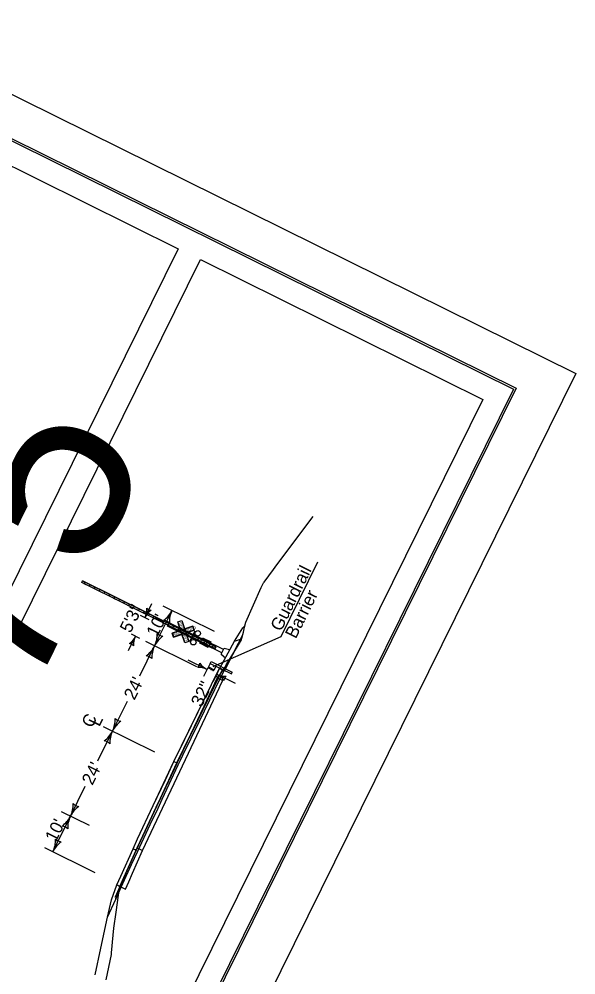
# Model space of a CAD drawing. Extents: x 14090526 to 14125274, y 8637242 to 8677144.
# Drawn here: x 14119513 to 14120076, y 8672010 to 8672975 of the extents above; entities that cross this region are included whole.
import ezdxf

# ---------------------------------------------------------------- set-up
doc = ezdxf.new("R2010")
doc.units = 0
for name, color, linetype in [('dsnCellElements', 7, 'Continuous'), ('dsnNonPlotable', 7, 'Continuous'), ('dsnShadingGranular', 7, 'Continuous'), ('dsnShadingPaved', 7, 'Continuous'), ('dsnStdLineWork', 7, 'Continuous'), ('dsnStgShadingPropPav', 7, 'Continuous'), ('dsnTextOverlapEven', 7, 'Continuous'), ('Level 1', 7, 'Continuous'), ('TC_ExistingPavement', 7, 'Continuous'), ('TC_Grading', 7, 'Continuous'), ('TC_PCCPavement', 7, 'Continuous'), ('TC_ShoulderEarthFill', 7, 'Continuous'), ('TC_ShoulderGranular', 7, 'Continuous'), ('TC_Subbase', 7, 'Continuous'), ('Terrain', 7, 'Continuous')]:
    doc.layers.add(name, color=color, linetype=linetype)

# ---------------------------------------------------------------- blocks, each defined once
blk = doc.blocks.new('LT')
at = {"layer": 'dsnCellElements'}
for centre, radius, start, end in [((-3.56, 0), 1.64, 342.2666, 17.7333), ((0, 4.25), 4.25, 241.9275, 270), ((0, -4.25), 4.25, 90, 118.0725)]:
    blk.add_arc(centre, radius, start, end, dxfattribs=at)

msp = doc.modelspace()

# ---------------------------------------------------------------- linework, layer by layer
at = {"layer": 'dsnNonPlotable'}
for points in [[(14118795.85, 8671851.12), (14119351.63, 8672975.23), (14120075.94, 8672617.11), (14119520.16, 8671493)], [(14118861.25, 8671870.1), (14119378.04, 8672915.32), (14120012.79, 8672601.49), (14119496.01, 8671556.26)]]:
    msp.add_lwpolyline(points, close=True, dxfattribs=at)
at = {"layer": 'dsnShadingGranular'}
msp.add_lwpolyline([(14119715.95, 8672319.65), (14119730.76, 8672346.82), (14119736.95, 8672348.92), (14119720.56, 8672317.37)], close=True, dxfattribs=at)
at = {"layer": 'dsnShadingPaved'}
msp.add_lwpolyline([(14119628.32, 8672137.28), (14119632.92, 8672147.07), (14119648.73, 8672180.74), (14119669.66, 8672225.31), (14119707.43, 8672303.02), (14119711.59, 8672311.67), (14119714.58, 8672310.19), (14119693.62, 8672267.01), (14119672.65, 8672223.83), (14119655.9, 8672188.16), (14119651.72, 8672179.26), (14119631.31, 8672135.8)], close=True, dxfattribs=at)
at = {"layer": 'dsnStdLineWork'}
for p, q in [((14119576.51, 8672406.12), (14119577.33, 8672407.78)), ((14119710.97, 8672339.64), (14119576.51, 8672406.12)), ((14119711.8, 8672341.3), (14119577.33, 8672407.78)), ((14119663.25, 8672362.2), (14119664.89, 8672365.52)), ((14119718.04, 8672335.12), (14119663.25, 8672362.2)), ((14119719.68, 8672338.44), (14119664.89, 8672365.52)), ((14119690.34, 8672356.71), (14119685.7, 8672347.33)), ((14119690.55, 8672356.09), (14119686.32, 8672347.54)), ((14119691.29, 8672356.24), (14119690.34, 8672356.71)), ((14119691.09, 8672355.83), (14119690.55, 8672356.09)), ((14119686.66, 8672346.86), (14119685.7, 8672347.33)), ((14119686.86, 8672347.28), (14119686.32, 8672347.54)), ((14119710.97, 8672339.64), (14119711.8, 8672341.3)), ((14119717.42, 8672333.87), (14119720.29, 8672339.68)), ((14119717.42, 8672333.87), (14119721.78, 8672330.16)), ((14119720.29, 8672339.68), (14119725.89, 8672338.46))]:
    msp.add_line(p, q, dxfattribs=at)
for points in [[(14119576.51, 8672406.12), (14119577.33, 8672407.78), (14119711.8, 8672341.3), (14119710.97, 8672339.64)], [(14119579, 8672404.89), (14119579.82, 8672406.55), (14119584.8, 8672404.09), (14119583.98, 8672402.43)], [(14119588.96, 8672399.97), (14119589.78, 8672401.63), (14119594.76, 8672399.17), (14119593.94, 8672397.51)], [(14119598.92, 8672395.04), (14119599.74, 8672396.7), (14119604.72, 8672394.24), (14119603.9, 8672392.58)], [(14119608.88, 8672390.12), (14119609.7, 8672391.78), (14119614.68, 8672389.32), (14119613.86, 8672387.66)], [(14119618.84, 8672385.19), (14119619.66, 8672386.85), (14119624.64, 8672384.39), (14119623.82, 8672382.73)], [(14119628.8, 8672380.27), (14119629.62, 8672381.93), (14119634.6, 8672379.47), (14119633.78, 8672377.81)], [(14119638.76, 8672375.35), (14119639.58, 8672377.01), (14119644.56, 8672374.54), (14119643.74, 8672372.88)], [(14119648.72, 8672370.42), (14119649.54, 8672372.08), (14119654.52, 8672369.62), (14119653.7, 8672367.96)], [(14119658.68, 8672365.5), (14119659.5, 8672367.16), (14119664.48, 8672364.69), (14119663.66, 8672363.03)], [(14119680.6, 8672345.28), (14119677.71, 8672353.83), (14119669.16, 8672350.94), (14119667.82, 8672354.89), (14119676.37, 8672357.78), (14119673.48, 8672366.33), (14119677.43, 8672367.67), (14119680.32, 8672359.12), (14119688.87, 8672362.01), (14119690.21, 8672358.06), (14119681.65, 8672355.17), (14119684.55, 8672346.62)], [(14119667.82, 8672354.89), (14119669.16, 8672350.94), (14119690.21, 8672358.06), (14119688.87, 8672362.01)], [(14119668.64, 8672360.57), (14119669.46, 8672362.23), (14119674.44, 8672359.77), (14119673.62, 8672358.11)], [(14119673.48, 8672366.33), (14119677.43, 8672367.67), (14119684.55, 8672346.62), (14119680.6, 8672345.28)], [(14119678.6, 8672355.65), (14119679.42, 8672357.31), (14119684.4, 8672354.84), (14119683.58, 8672353.18)], [(14119688.56, 8672350.72), (14119689.38, 8672352.38), (14119694.36, 8672349.92), (14119693.54, 8672348.26)], [(14119695.91, 8672344.71), (14119698.62, 8672350.19), (14119706.94, 8672346.08), (14119704.23, 8672340.6)], [(14119695.91, 8672344.71), (14119698.62, 8672350.19), (14119706.94, 8672346.08), (14119704.23, 8672340.6)], [(14119708.48, 8672340.87), (14119709.31, 8672342.53), (14119711.8, 8672341.3), (14119710.97, 8672339.64)]]:
    msp.add_lwpolyline(points, close=True, dxfattribs=at)
for centre, radius in [((14119693.68, 8672354.8), 2.78), ((14119693.68, 8672354.8), 2.78), ((14119689.25, 8672345.84), 2.78), ((14119689.25, 8672345.84), 2.78), ((14119701.42, 8672345.4), 1.39)]:
    msp.add_circle(centre, radius, dxfattribs=at)
at = {"layer": 'dsnStgShadingPropPav'}
for points in [[(14119711.59, 8672311.67), (14119715.95, 8672319.65), (14119718.93, 8672318.18), (14119714.58, 8672310.19)], [(14119612.03, 8672100.71), (14119615.99, 8672109.61), (14119628.24, 8672137.11), (14119631.31, 8672135.8), (14119618.98, 8672108.13), (14119615.01, 8672099.23)]]:
    msp.add_lwpolyline(points, close=True, dxfattribs=at)
at = {"layer": 'dsnTextOverlapEven'}
for p, q in [((14119640.15, 8672370.63), (14119647.24, 8672384.98)), ((14119710.54, 8672356.81), (14119658.8, 8672382.4)), ((14119644.42, 8672368.52), (14119635.88, 8672372.74)), ((14119650.01, 8672342.04), (14119667.77, 8672377.96)), ((14119623.75, 8672337.46), (14119630.84, 8672351.81)), ((14119635.11, 8672349.7), (14119626.57, 8672353.92)), ((14119635.17, 8672312.04), (14119650.01, 8672342.04)), ((14119692.81, 8672320.96), (14119641.07, 8672346.54)), ((14119703.17, 8672318.35), (14119684.01, 8672327.82)), ((14119706.2, 8672324.47), (14119704.43, 8672320.89)), ((14119706.2, 8672324.47), (14119707.09, 8672326.26)), ((14119706.2, 8672324.47), (14119727.72, 8672313.83)), ((14119707.09, 8672326.26), (14119728.6, 8672315.63)), ((14119711.88, 8672321.66), (14119710.11, 8672318.08)), ((14119703.95, 8672319.91), (14119699.57, 8672311.05)), ((14119704.43, 8672320.89), (14119710.41, 8672317.93)), ((14119713.55, 8672315.17), (14119709.17, 8672306.3)), ((14119731.94, 8672304.12), (14119712.77, 8672313.6)), ((14119727.72, 8672313.83), (14119728.6, 8672315.63)), ((14119607.49, 8672256.05), (14119622.51, 8672286.43)), ((14119592.66, 8672226.05), (14119607.49, 8672256.05)), ((14119650.27, 8672234.9), (14119598.53, 8672260.48)), ((14119564.97, 8672170.06), (14119579.99, 8672200.44)), ((14119547.25, 8672134.2), (14119564.97, 8672170.06)), ((14119584.22, 8672160.54), (14119556.01, 8672174.49)), ((14119590.02, 8672113.05), (14119538.97, 8672138.3))]:
    msp.add_line(p, q, dxfattribs=at)
for points in [[(14118892.07, 8671880.52), (14119388.46, 8672884.51), (14119674.02, 8672743.33), (14119177.62, 8671739.34)], [(14119200.03, 8671728.26), (14119696.43, 8672732.25), (14119981.98, 8672591.06), (14119485.59, 8671587.07)]]:
    msp.add_lwpolyline(points, close=True, dxfattribs=at)
msp.add_lwpolyline([(14119814.8, 8672426.56), (14119777.6, 8672351.31), (14119709.08, 8672321.05)], dxfattribs=at)
for centre, major_axis, ratio, start_param, end_param in [((14119705.35, 8672320.43), (-0.48, -0.971), 0.951924, 4.712389, 7.853982), ((14119707.42, 8672319.41), (-1.14, 0.56), 0.852459, 0, 3.141593), ((14119709.48, 8672318.39), (-0.481, -0.973), 0.949899, 4.712389, 7.853982)]:
    msp.add_ellipse(centre, major_axis=major_axis, ratio=ratio, start_param=start_param, end_param=end_param, dxfattribs=at)
at = {"layer": 'Level 1'}
msp.add_lwpolyline([(14118858.58, 8671869.19), (14119377.13, 8672918), (14120015.47, 8672602.39), (14119496.92, 8671553.58)], close=True, dxfattribs=at)
at = {"layer": 'TC_ExistingPavement'}
for p, q in [((14119713.6, 8672309.78), (14119718.98, 8672307.12)), ((14119632.48, 8672138.09), (14119637.86, 8672135.43)), ((14119615.32, 8672099.08), (14119620.7, 8672096.42))]:
    msp.add_line(p, q, dxfattribs=at)
msp.add_lwpolyline([(14119620.7, 8672096.42), (14119623.96, 8672103.8), (14119627.83, 8672112.55), (14119637.86, 8672135.43), (14119695.73, 8672257.96), (14119715.25, 8672299.48), (14119717.16, 8672303.4), (14119718.98, 8672307.12)], dxfattribs=at)
at = {"layer": 'TC_Grading'}
for points in [[(14119730.76, 8672346.82), (14119739.28, 8672360.45), (14119741.34, 8672362.53)], [(14119589.87, 8672009.77), (14119595.71, 8672036.63), (14119602.57, 8672068.2), (14119606.37, 8672085.66), (14119612.03, 8672100.71)]]:
    msp.add_lwpolyline(points, dxfattribs=at)
at = {"layer": 'TC_PCCPavement'}
for p, q in [((14119714.58, 8672310.19), (14119718.77, 8672317.88)), ((14119715.79, 8672319.36), (14119715.95, 8672319.65)), ((14119715.79, 8672319.36), (14119718.77, 8672317.88)), ((14119718.77, 8672317.88), (14119718.93, 8672318.18)), ((14119672.65, 8672223.83), (14119714.58, 8672310.19)), ((14119711.59, 8672311.67), (14119714.58, 8672310.19)), ((14119669.66, 8672225.31), (14119672.65, 8672223.83)), ((14119628.32, 8672137.28), (14119631.31, 8672135.8)), ((14119612.03, 8672100.71), (14119615.01, 8672099.23))]:
    msp.add_line(p, q, dxfattribs=at)
for points in [[(14119612.03, 8672100.71), (14119615.99, 8672109.61), (14119628.32, 8672137.28), (14119632.92, 8672147.07), (14119648.73, 8672180.74), (14119661.02, 8672206.92), (14119669.66, 8672225.31), (14119673.83, 8672233.96), (14119707.43, 8672303.02), (14119711.59, 8672311.67), (14119715.79, 8672319.36)], [(14119615.01, 8672099.23), (14119618.98, 8672108.13), (14119631.31, 8672135.8), (14119651.72, 8672179.26), (14119655.9, 8672188.16), (14119672.65, 8672223.83)]]:
    msp.add_lwpolyline(points, dxfattribs=at)
at = {"layer": 'TC_ShoulderEarthFill'}
for p, q in [((14119736.95, 8672348.92), (14119739.03, 8672352.91)), ((14119602.57, 8672068.2), (14119610.82, 8672086.22))]:
    msp.add_line(p, q, dxfattribs=at)
at = {"layer": 'TC_ShoulderGranular'}
for p, q in [((14119715.95, 8672319.65), (14119730.76, 8672346.82)), ((14119730.76, 8672346.82), (14119736.95, 8672348.92))]:
    msp.add_line(p, q, dxfattribs=at)
at = {"layer": 'TC_Subbase'}
msp.add_line((14119716.38, 8672309.31), (14119734.82, 8672344.81), dxfattribs=at)
for points in [[(14119734.82, 8672344.81), (14119735.92, 8672346.93), (14119736.95, 8672348.92)], [(14119610.82, 8672086.22), (14119616.34, 8672098.27), (14119626.8, 8672121.15), (14119633.1, 8672134.92), (14119645.6, 8672161.54), (14119653.51, 8672178.37), (14119657.69, 8672187.28), (14119673.92, 8672221.83), (14119676.53, 8672227.27), (14119678.61, 8672231.6), (14119695.41, 8672266.13), (14119716.38, 8672309.31)], [(14119615.01, 8672099.23), (14119610.13, 8672088.26), (14119610.82, 8672086.22)]]:
    msp.add_lwpolyline(points, dxfattribs=at)
at = {"layer": 'Terrain'}
msp.add_lwpolyline([(14119601.24, 8672004.65), (14119606.52, 8672030.41), (14119606.65, 8672032.02), (14119608.12, 8672049.99), (14119608.83, 8672056.87), (14119611.06, 8672073.16), (14119614.71, 8672097.7), (14119618.58, 8672106.46), (14119622.45, 8672115.21), (14119627.47, 8672126.65), (14119632.48, 8672138.09), (14119661.42, 8672199.35), (14119690.35, 8672260.62), (14119700.11, 8672281.38), (14119709.87, 8672302.14), (14119711.78, 8672306.05), (14119713.6, 8672309.78), (14119714.48, 8672311.54), (14119717.31, 8672315.02), (14119720.89, 8672320.45), (14119722.55, 8672323.03), (14119729.27, 8672333.91), (14119735.99, 8672344.79), (14119737.4, 8672347.62), (14119739.96, 8672355.92), (14119741.04, 8672361.08), (14119742.12, 8672366.23), (14119750.02, 8672383.68), (14119757.92, 8672401.12), (14119760.07, 8672405.74), (14119760.77, 8672406.58), (14119770.27, 8672419.29), (14119773.77, 8672423.85), (14119810.23, 8672472.98)], dxfattribs=at)

# ---------------------------------------------------------------- block references
at = {"layer": 'dsnTextOverlapEven'}
for p, xscale, yscale, rotation in [((14119640.15, 8672370.63), 4.731057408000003, 4.731057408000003, -116.30889254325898), ((14119667.73, 8672377.9), 6.308076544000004, 6.308076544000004, 63.69110745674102), ((14119630.84, 8672351.81), 4.7310574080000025, 4.7310574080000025, 63.69110745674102), ((14119650.01, 8672342.04), 6.308076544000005, 6.308076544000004, -116.30889254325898), ((14119650.01, 8672342.04), 6.308076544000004, 6.308076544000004, 63.69110745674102), ((14119703.17, 8672318.35), 4.7310574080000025, 4.731057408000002, -26.30889254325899), ((14119712.77, 8672313.6), 4.7310574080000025, 4.7310574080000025, 153.691107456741), ((14119607.49, 8672256.05), 6.308076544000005, 6.308076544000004, -116.30889254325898), ((14119607.49, 8672256.05), 6.308076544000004, 6.308076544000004, 63.69110745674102), ((14119564.97, 8672170.06), 6.308076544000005, 6.308076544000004, -116.30889254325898), ((14119564.97, 8672170.06), 6.308076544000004, 6.308076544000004, 63.69110745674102), ((14119547.25, 8672134.2), 6.308076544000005, 6.308076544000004, -116.30889254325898)]:
    msp.add_blockref('LT', p, dxfattribs=dict(at, xscale=xscale, yscale=yscale, rotation=rotation))

# ---------------------------------------------------------------- texts
at = {"layer": 'dsnStdLineWork'}
for s, rotation, p in [('CROSSING', 108.69117, (14119683.62, 8672347.21)), ('ROAD', 18.69117, (14119681.86, 8672355.97)), ('RAIL', 18.69117, (14119669.36, 8672351.74))]:
    msp.add_text(s, height=2.778, rotation=rotation, dxfattribs=at).set_placement(p)
at = {"layer": 'dsnTextOverlapEven'}
for s, rotation, p in [('Guardrail', 63.69123, (14119777.91, 8672355.96)), ('Barrier', 63.69123, (14119792.82, 8672348.58)), ('5\'3"', 63.69111, (14119625.7, 8672354.36)), ("10'", 63.69111, (14119652.52, 8672350.1)), ("24'", 63.69111, (14119629.72, 8672286.57)), ('32"', 63.69111, (14119697.55, 8672279.66)), ('C', 63.69111, (14119586.99, 8672258.41)), ('L', 63.69111, (14119594.18, 8672259.83)), ("24'", 63.69111, (14119587.2, 8672200.58)), ("10'", 63.69111, (14119550.17, 8672143.07))]:
    msp.add_text(s, height=12.8, rotation=rotation, dxfattribs=at).set_placement(p)
at = {"layer": 'TC_PCCPavement'}
msp.add_text('US 75', height=192, rotation=63.69117, dxfattribs=at).set_placement((14119331.71, 8671898.58))

doc.saveas('drawing.dxf')
